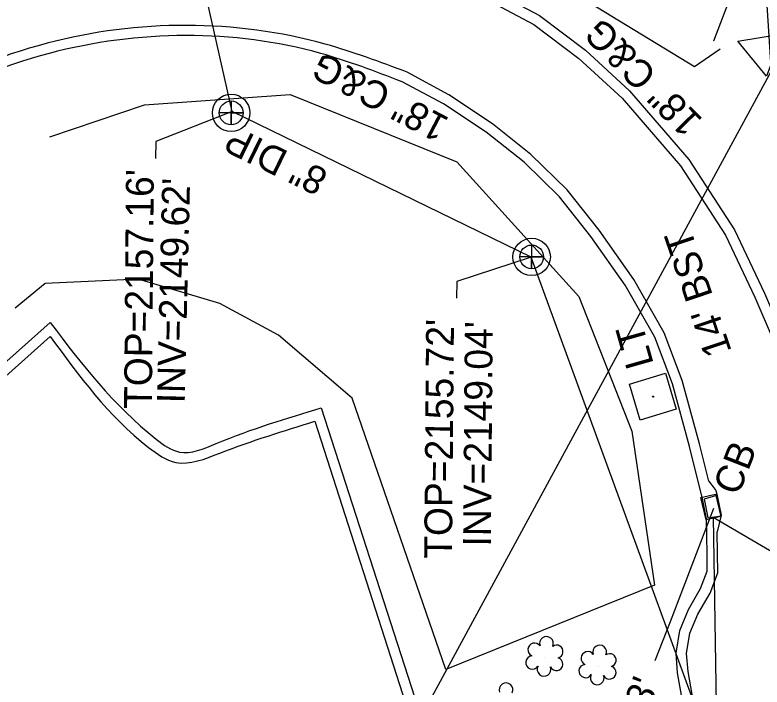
# Model space of a CAD drawing. Extents: x 945964 to 948456, y 631061 to 636061.
# Drawn here: x 946648 to 946755.3, y 632663.5 to 632760.1 of the extents above; entities that cross this region are included whole.
import ezdxf

# ---------------------------------------------------------------- set-up
doc = ezdxf.new("R2010")
doc.units = 0
for name, color, linetype in [('Exist Right of Way Line', 7, 'Continuous'), ('Exist Right of Way Monument CELL', 7, 'Continuous'), ('Exist Roads Curbs', 7, 'Continuous'), ('Exist Roads Curbs Text', 7, 'Continuous'), ('Exist Roads EOP', 7, 'Continuous'), ('Exist Roads EOP Text', 7, 'Continuous'), ('Exist Structure Minor Catch Basin', 7, 'Continuous'), ('Exist Structure Minor Catch Basin Text', 7, 'Continuous'), ('Exist Structure Minor Catch Basin Top Elevation', 7, 'Continuous'), ('Exist Structure Minor Drop Inlet', 7, 'Continuous'), ('Exist Structure Minor Pipes RCP 15 Inch', 7, 'Continuous'), ('Exist Structure Minor Pipes RCP 15 Inch Invert', 7, 'Continuous'), ('Exist Utilities Other Pole With Base CELL', 7, 'Continuous'), ('Exist Utilities Other Pole With Base Text', 7, 'Continuous'), ('Exist Utilities Sanitary Sewer Manhole CELL', 7, 'Continuous'), ('Exist Utilities Sanitary Sewer Manhole Text', 7, 'Continuous'), ('Exist Utilities Sanitary Sewer UG Line', 7, 'Continuous'), ('Exist Utilities Sanitary Sewer UG Line Invert Elevation', 7, 'Continuous'), ('Exist Utilities Sanitary Sewer UG Line Text', 7, 'Continuous'), ('Exist Vegetation Hedge Row', 7, 'Continuous'), ('Exist Vegetation Shrub CELL', 7, 'Continuous'), ('Scratch_Level_5', 7, 'Continuous')]:
    doc.layers.add(name, color=color, linetype=linetype)

msp = doc.modelspace()

# ---------------------------------------------------------------- linework, layer by layer
at = {"layer": 'Exist Right of Way Line'}
msp.add_arc((948848.33, 632890.69), 2096.28, 158.90258, 198.31343, dxfattribs=at)
at = {"layer": 'Exist Right of Way Monument CELL'}
msp.add_lwpolyline([(946751.87, 632756.38), (946758.3, 632757.42), (946755.98, 632751.34)], close=True, dxfattribs=at)
at = {"layer": 'Exist Roads Curbs'}
for points in [[(946706.28, 632768.36), (946715.37, 632764.32), (946723.38, 632760.03), (946729.96, 632755.05), (946736.31, 632749.23), (946744.84, 632739.34), (946751.41, 632729.22), (946755.7, 632720.14), (946760.54, 632708.81), (946764.21, 632697.09), (946766.49, 632687.88), (946768.02, 632676.08), (946769.73, 632660.88), (946772.17, 632645.55), (946774.65, 632631.96)], [(946744.83, 632656.38), (946743.22, 632665.55), (946743, 632668.37), (946743.52, 632671.65), (946744.76, 632674.64), (946746.51, 632677.66), (946747.47, 632680.17), (946747.46, 632682.69), (946747.35, 632687.68), (946746.78, 632690.56), (946744.91, 632698.1), (946742.46, 632707.11), (946739.93, 632713.79), (946735.66, 632721.3), (946730.72, 632728.28), (946726.22, 632733.97), (946721.14, 632738.94), (946715.71, 632743.26), (946709.56, 632747.37), (946703.61, 632750.53)], [(946540.73, 632597.65), (946532.17, 632608.11), (946563.81, 632636.17), (946596.51, 632665.44), (946625.91, 632691.7), (946653.07, 632715.9)], [(946691.99, 632703.63), (946705.92, 632660.47), (946717.76, 632624.89), (946731.3, 632584.34)]]:
    msp.add_lwpolyline(points, dxfattribs=at)
for points in [[(946625.23, 632781.62), (946610.39, 632758.96), (946609.55, 632757.41), (946608.96, 632755.65), (946608.8, 632753.95), (946608.95, 632753.22), (946609.09, 632752.9), (946609.29, 632752.61), (946609.82, 632752.22), (946610.51, 632752.09), (946612.19, 632752.42), (946613.97, 632753.22), (946615.47, 632754.15), (946617.55, 632755.82), (946619.49, 632757.73), (946623.22, 632761.9), (946627.2, 632765.89), (946629.47, 632767.58), (946630.7, 632768.31), (946632, 632768.94), (946642.15, 632772.77), (946652.39, 632775.41), (946662.64, 632776.68), (946667.74, 632776.75), (946672.82, 632776.41), (946681.32, 632775.38), (946689.91, 632773.88), (946706.28, 632768.36)], [(946703.61, 632750.53), (946691.95, 632754.59), (946652.91, 632754.59), (946615.96, 632734.07), (946602.97, 632720.97)], [(946653.07, 632715.9), (946668.29, 632699.14), (946671.62, 632697.28), (946676.9, 632698.51), (946691.99, 632703.63)]]:
    msp.add_spline(points, degree=3, dxfattribs=at)
at = {"layer": 'Exist Roads EOP'}
for points in [[(946705.43, 632767.12), (946714.71, 632762.97), (946722.57, 632758.76), (946729, 632753.89), (946735.23, 632748.18), (946743.64, 632738.44), (946750.1, 632728.49), (946754.33, 632719.53), (946759.13, 632708.29), (946762.77, 632696.69), (946765.01, 632687.6), (946766.53, 632675.9), (946768.25, 632660.68), (946770.69, 632645.3), (946773.24, 632631.64)], [(946747.69, 632693.12), (946746.36, 632698.47), (946743.88, 632707.57), (946741.29, 632714.43), (946736.93, 632722.1), (946731.92, 632729.18), (946727.33, 632734.98), (946722.14, 632740.06), (946716.59, 632744.47), (946710.33, 632748.66), (946704.35, 632751.9)], [(946541.71, 632598.56), (946534.02, 632608.09), (946564.77, 632634.95), (946597.67, 632664.16), (946627.03, 632690.66), (946653.05, 632713.92)], [(946691.06, 632701.71), (946704.53, 632659.84), (946716.45, 632623.99), (946729.93, 632583.46)], [(946747.69, 632693.12), (946748.71, 632691.78), (946748.84, 632691.23), (946749.49, 632688.22), (946748.89, 632685.84)], [(946757.63, 632618.81), (946754.41, 632621.85), (946752.55, 632624.32), (946751.47, 632626.77), (946750.93, 632630.95), (946748.48, 632644.02), (946746.31, 632656.64), (946744.71, 632665.74), (946744.51, 632668.31), (946744.97, 632671.24), (946746.11, 632673.98), (946747.87, 632677.01), (946748.97, 632679.9), (946748.96, 632682.71), (946748.89, 632685.84)]]:
    msp.add_lwpolyline(points, dxfattribs=at)
for points in [[(946624.15, 632782.33), (946609.23, 632759.71), (946608.22, 632757.71), (946607.61, 632755.41), (946607.6, 632753.2), (946607.89, 632752.24), (946608.12, 632751.82), (946608.41, 632751.44), (946609.15, 632750.93), (946610.07, 632750.73), (946612.24, 632751.08), (946614.5, 632752.05), (946616.43, 632753.2), (946618.49, 632754.81), (946620.42, 632756.67), (946624.12, 632760.76), (946628.07, 632764.68), (946630.3, 632766.33), (946631.51, 632767.03), (946632.8, 632767.64), (946642.79, 632771.3), (946652.87, 632773.83), (946662.95, 632775.06), (946667.97, 632775.12), (946672.96, 632774.79), (946681.21, 632773.78), (946689.52, 632772.36), (946705.43, 632767.12)], [(946704.35, 632751.9), (946692.58, 632755.93), (946652.6, 632756.06), (946615.44, 632735.47), (946601.95, 632722.05)], [(946653.05, 632713.92), (946667.19, 632697.95), (946671.09, 632695.8), (946677.43, 632697.13), (946691.06, 632701.71)]]:
    msp.add_spline(points, degree=3, dxfattribs=at)
at = {"layer": 'Exist Structure Minor Catch Basin'}
msp.add_lwpolyline([(946747.57, 632687.82), (946749.45, 632688.1), (946748.82, 632691.04), (946747.04, 632690.52), (946747.57, 632687.82)], dxfattribs=at)
at = {"layer": 'Exist Structure Minor Catch Basin Top Elevation'}
msp.add_lwpolyline([(946748.38, 632689.15), (946742.13, 632672.87), (946739.95, 632667.28)], dxfattribs=at)
at = {"layer": 'Exist Structure Minor Drop Inlet'}
msp.add_lwpolyline([(946748.67, 632691.24), (946749.42, 632688.04), (946747.3, 632687.55), (946746.55, 632690.74)], close=True, dxfattribs=at)
at = {"layer": 'Exist Structure Minor Pipes RCP 15 Inch'}
msp.add_line((946748.31, 632687.92), (946750.9, 632523.21), dxfattribs=at)
at = {"layer": 'Exist Structure Minor Pipes RCP 15 Inch Invert'}
msp.add_lwpolyline([(946748.31, 632687.92), (946762.79, 632679.46), (946764.98, 632685.05)], dxfattribs=at)
at = {"layer": 'Exist Utilities Other Pole With Base CELL'}
msp.add_line((946739.68, 632705.25), (946739.68, 632705.25), dxfattribs=at)
msp.add_lwpolyline([(946736.29, 632707.05), (946741.45, 632708.61), (946743.02, 632703.45), (946737.85, 632701.88), (946736.29, 632707.05)], dxfattribs=at)
msp.add_circle((946739.68, 632705.25), 0.0707, dxfattribs=at)
at = {"layer": 'Exist Utilities Sanitary Sewer Manhole CELL'}
for points in [[(946679.05, 632747.76), (946679.05, 632744.33), (946679.05, 632746.05), (946680.77, 632746.05), (946677.34, 632746.05)], [(946722.24, 632727.05), (946722.24, 632723.63), (946722.24, 632725.34), (946723.95, 632725.34), (946720.53, 632725.34)]]:
    msp.add_lwpolyline(points, dxfattribs=at)
for centre, radius in [((946679.05, 632746.05), 2.69), ((946679.05, 632746.05), 1.71), ((946722.24, 632725.34), 2.69), ((946722.24, 632725.34), 1.71)]:
    msp.add_circle(centre, radius, dxfattribs=at)
at = {"layer": 'Exist Utilities Sanitary Sewer Manhole Text'}
for points in [[(946679.18, 632746.23), (946668.22, 632741.93), (946668.2, 632739.5)], [(946722.19, 632725.3), (946711.48, 632721.81), (946711.46, 632719.39)]]:
    msp.add_lwpolyline(points, dxfattribs=at)
at = {"layer": 'Exist Utilities Sanitary Sewer UG Line'}
for points in [[(946679.18, 632746.23), (946648.81, 632881.02)], [(946722.19, 632725.3), (946679.18, 632746.23)], [(946773.84, 632583.86), (946722.19, 632725.3)]]:
    msp.add_lwpolyline(points, dxfattribs=at)
at = {"layer": 'Exist Vegetation Hedge Row'}
for points in [[(946749.35, 632755.23), (946745.64, 632752.67), (946721.89, 632767.19), (946719.51, 632773.98), (946719.95, 632782), (946723.67, 632790.32), (946729.78, 632792.58), (946737.88, 632786.15)], [(946737.36, 632785.3), (946745.19, 632779.38), (946750.48, 632772.59), (946751.01, 632763.31), (946748.37, 632756.35), (946748.37, 632756.35)], [(946653, 632742.62), (946666.61, 632747.19), (946687.53, 632748.7), (946711.47, 632739), (946729.01, 632719.65), (946736.64, 632700.29), (946739.91, 632678.14), (946709.92, 632666.01), (946696.47, 632705.04), (946685.85, 632714.11), (946677.41, 632718.63), (946665.7, 632722.12), (946652.33, 632721.52), (946648.04, 632717.98)]]:
    msp.add_lwpolyline(points, dxfattribs=at)
at = {"layer": 'Exist Vegetation Shrub CELL'}
for p, q in [((946724.14, 632667.73), (946724.14, 632667.73)), ((946731.79, 632666.5), (946731.79, 632666.5))]:
    msp.add_line(p, q, dxfattribs=at)
for centre, radius, start, end in [((946724.37, 632669.77), 0.99, 334.8391, 200.4717), ((946722.66, 632668.86), 0.968, 35.8908, 245.4216), ((946725.82, 632668.6), 0.929, 284.4567, 126.0861), ((946732.02, 632668.54), 0.99, 334.8391, 200.4717), ((946730.31, 632667.63), 0.968, 35.8908, 245.4216), ((946722.34, 632667.02), 0.955, 95.1099, 327.9534), ((946725.78, 632666.8), 0.937, 204.9913, 73.4601), ((946733.46, 632667.37), 0.929, 284.4567, 126.0861), ((946724.02, 632666.04), 0.984, 151.2797, 21.387), ((946729.99, 632665.8), 0.955, 95.1099, 327.9534), ((946733.43, 632665.58), 0.937, 204.9913, 73.4601), ((946731.66, 632664.82), 0.984, 151.2797, 21.387), ((946718.55, 632663.1), 0.99, 334.8391, 200.4717)]:
    msp.add_arc(centre, radius, start, end, dxfattribs=at)
at = {"layer": 'Scratch_Level_5'}
msp.add_line((946765.74, 632768.87), (946694.09, 632636.66), dxfattribs=at)

# ---------------------------------------------------------------- texts
at = {"layer": 'Exist Roads Curbs Text'}
for rotation, p in [(134.6271, (946746.99, 632745.06)), (152.3762, (946710.58, 632745.22))]:
    msp.add_text('18" C&G', height=4, rotation=rotation, dxfattribs=at).set_placement(p)
at = {"layer": 'Exist Roads EOP Text'}
msp.add_text("14' BST", height=4, rotation=108.6303, dxfattribs=at).set_placement((946751.03, 632711.77))
at = {"layer": 'Exist Structure Minor Catch Basin Text'}
msp.add_text('CB', height=4, rotation=68.619, dxfattribs=at).set_placement((946751.94, 632690.87))
at = {"layer": 'Exist Structure Minor Catch Basin Top Elevation'}
msp.add_text("TOP=2154.73'", height=4, rotation=68.6189, dxfattribs=at).set_placement((946728.12, 632631.79))
at = {"layer": 'Exist Utilities Other Pole With Base Text'}
msp.add_text('LT', height=4, rotation=105.8467, dxfattribs=at).set_placement((946739.81, 632709.96))
at = {"layer": 'Exist Utilities Sanitary Sewer Manhole Text'}
for s, p in [("TOP=2157.16'", (946667.66, 632703.47)), ("TOP=2155.72'", (946710.79, 632681.93))]:
    msp.add_text(s, height=4, rotation=89.5187, dxfattribs=at).set_placement(p)
at = {"layer": 'Exist Utilities Sanitary Sewer UG Line Invert Elevation'}
for s, rotation, p in [("INV=2149.62'", 88.6197, (946672.38, 632704.25)), ("INV=2149.04'", 89.5187, (946716.38, 632683.69))]:
    msp.add_text(s, height=4, rotation=rotation, dxfattribs=at).set_placement(p)
at = {"layer": 'Exist Utilities Sanitary Sewer UG Line Text'}
msp.add_text('8" DIP', height=4, rotation=154.056, dxfattribs=at).set_placement((946693.2, 632737.62))

doc.saveas('drawing.dxf')
